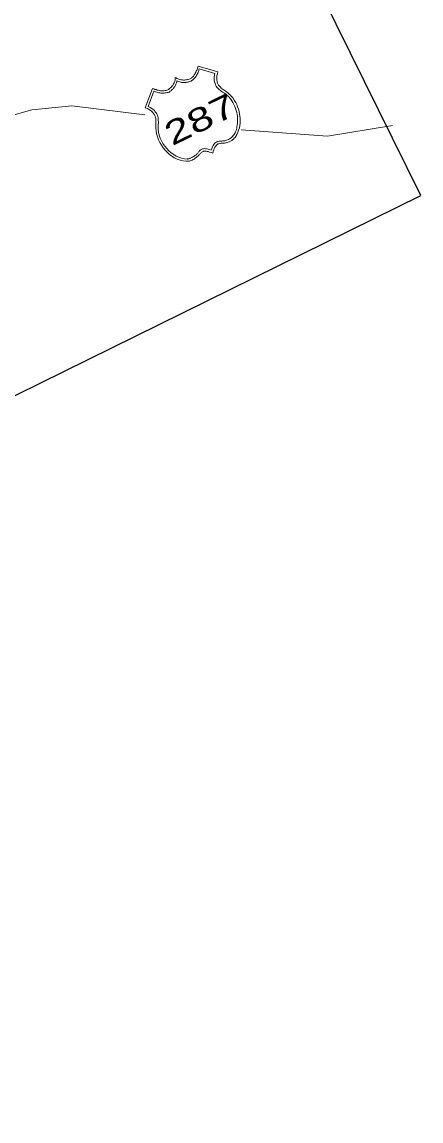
# Model space of a CAD drawing. Extents: x 2356606 to 2371222, y 6973096 to 6982644.
# Drawn here: x 2371136.4 to 2371222.1, y 6980110.7 to 6980347 of the extents above; entities that cross this region are included whole.
import ezdxf

# ---------------------------------------------------------------- set-up
doc = ezdxf.new("R2010")
doc.units = 0
doc.header["$LTSCALE"] = 2
doc.layers.add('62', color=7, linetype='Continuous', lineweight=13)
doc.layers.add('63', color=7, linetype='Continuous', lineweight=13)

msp = doc.modelspace()

# ---------------------------------------------------------------- linework, layer by layer
at = {"layer": '62'}
for p, q in [((2371147.148, 6980328.917), (2371162.799, 6980327.005)), ((2371215.993, 6980324.674), (2371202.01, 6980322.445)), ((2371202.01, 6980322.445), (2371183.47, 6980323.757))]:
    msp.add_line(p, q, dxfattribs=at)
at = {"layer": '62', "lineweight": 25}
msp.add_lwpolyline([(2370613.001, 6980527.892), (2370818.917, 6980110.665), (2371222.081, 6980309.64), (2371016.165, 6980726.869)], dxfattribs=at)
at = {"layer": '62'}
for points in [[(2371147.148, 6980328.917), (2371138.571, 6980328.048), (2371129.118, 6980325.438), (2371112.027, 6980320.969), (2371100.06, 6980322.039), (2371091.911, 6980322.932), (2371081.3, 6980324.295), (2371069.258, 6980328.819), (2371059.239, 6980335.242), (2371048.852, 6980342.862), (2371035.27, 6980351.267), (2371024.817, 6980355.667), (2371015.947, 6980360.773), (2371005.588, 6980367.578), (2370999.855, 6980370.196), (2370987.882, 6980378.49)], [(2371162.878, 6980328.524), (2371164.477, 6980332.651), (2371164.72, 6980332.57), (2371164.969, 6980332.467), (2371165.22, 6980332.415), (2371165.442, 6980332.323), (2371165.696, 6980332.274), (2371165.916, 6980332.23), (2371166.136, 6980332.19), (2371166.377, 6980332.158), (2371166.559, 6980332.146), (2371166.78, 6980332.156), (2371166.982, 6980332.154), (2371167.185, 6980332.204), (2371167.366, 6980332.243), (2371167.524, 6980332.274), (2371167.728, 6980332.372), (2371167.909, 6980332.461), (2371168.011, 6980332.563), (2371168.131, 6980332.673), (2371168.282, 6980332.772), (2371168.414, 6980332.913), (2371168.547, 6980333.054), (2371168.647, 6980333.203), (2371168.781, 6980333.344), (2371168.901, 6980333.503), (2371168.983, 6980333.694), (2371169.085, 6980333.894), (2371169.167, 6980334.085), (2371169.257, 6980334.255), (2371169.288, 6980334.449), (2371169.339, 6980334.648), (2371169.311, 6980334.859), (2371169.341, 6980335.05), (2371169.511, 6980334.96), (2371169.703, 6980334.828), (2371169.903, 6980334.726), (2371170.085, 6980334.664), (2371170.297, 6980334.593), (2371170.516, 6980334.55), (2371170.707, 6980334.521), (2371170.919, 6980334.498), (2371171.127, 6980334.478), (2371171.32, 6980334.448), (2371171.542, 6980334.505), (2371171.725, 6980334.496), (2371171.966, 6980334.564), (2371172.127, 6980334.594), (2371172.348, 6980334.652), (2371172.521, 6980334.713), (2371172.661, 6980334.783), (2371172.832, 6980334.893), (2371172.924, 6980335.012), (2371173.084, 6980335.14), (2371173.216, 6980335.283), (2371173.318, 6980335.434), (2371173.421, 6980335.583), (2371173.552, 6980335.774), (2371173.634, 6980335.965), (2371173.744, 6980336.144), (2371173.816, 6980336.356), (2371173.937, 6980336.567), (2371174.011, 6980336.777), (2371174.09, 6980337.019), (2371174.152, 6980337.251), (2371174.244, 6980337.471), (2371178.496, 6980336.232), (2371178.372, 6980335.818), (2371178.249, 6980335.407), (2371178.235, 6980334.975), (2371178.275, 6980334.542), (2371178.303, 6980334.128), (2371178.389, 6980333.795), (2371178.52, 6980333.534), (2371178.61, 6980333.353), (2371178.732, 6980333.21), (2371178.881, 6980333.061), (2371179.021, 6980332.927), (2371179.201, 6980332.766), (2371179.4, 6980332.614), (2371179.602, 6980332.462), (2371179.834, 6980332.301), (2371180.063, 6980332.139), (2371180.304, 6980331.954), (2371180.535, 6980331.794), (2371180.765, 6980331.58), (2371180.975, 6980331.407), (2371181.165, 6980331.225), (2371181.355, 6980331.044), (2371181.536, 6980330.831), (2371181.684, 6980330.63), (2371181.995, 6980330.155), (2371182.307, 6980329.681), (2371182.534, 6980329.216), (2371182.711, 6980328.703), (2371182.911, 6980328.199), (2371183.05, 6980327.714), (2371183.147, 6980327.21), (2371183.224, 6980326.698), (2371183.293, 6980326.205), (2371183.3, 6980325.68)], [(2371182.569, 6980324.468), (2371182.651, 6980324.758), (2371182.674, 6980325.122), (2371182.695, 6980325.482), (2371182.707, 6980325.865), (2371182.69, 6980326.257), (2371182.662, 6980326.67), (2371182.615, 6980327.073), (2371182.523, 6980327.506), (2371182.427, 6980327.959), (2371182.277, 6980328.363), (2371182.127, 6980328.815), (2371181.921, 6980329.242), (2371181.681, 6980329.673), (2371181.45, 6980330.038), (2371181.232, 6980330.38), (2371180.982, 6980330.633), (2371180.741, 6980330.915), (2371180.48, 6980331.14), (2371180.251, 6980331.352), (2371179.999, 6980331.554), (2371179.739, 6980331.725), (2371179.479, 6980331.899), (2371179.257, 6980332.042), (2371179.047, 6980332.214), (2371178.837, 6980332.386), (2371178.616, 6980332.576), (2371178.457, 6980332.749), (2371178.286, 6980332.942), (2371178.125, 6980333.164), (2371177.966, 6980333.437), (2371177.878, 6980333.77), (2371177.789, 6980334.102), (2371177.721, 6980334.444), (2371177.682, 6980334.825), (2371177.714, 6980335.169), (2371177.787, 6980335.532), (2371177.858, 6980335.893), (2371174.493, 6980336.917), (2371174.423, 6980336.706), (2371174.37, 6980336.503), (2371174.309, 6980336.273), (2371174.228, 6980336.081), (2371174.137, 6980335.863), (2371174.024, 6980335.682), (2371173.914, 6980335.502), (2371173.801, 6980335.32), (2371173.669, 6980335.13), (2371173.557, 6980334.95), (2371173.404, 6980334.798), (2371173.265, 6980334.679), (2371173.132, 6980334.537), (2371173.002, 6980334.449), (2371172.872, 6980334.359), (2371172.739, 6980334.267), (2371172.588, 6980334.22), (2371172.415, 6980334.16), (2371172.236, 6980334.07), (2371172.072, 6980334.041), (2371171.841, 6980334.002), (2371171.68, 6980333.972), (2371171.489, 6980333.953), (2371171.269, 6980333.943), (2371171.086, 6980333.955), (2371170.865, 6980333.947), (2371170.696, 6980333.987), (2371170.494, 6980334.04), (2371170.283, 6980334.061), (2371170.093, 6980334.143), (2371169.902, 6980334.223), (2371169.701, 6980334.326), (2371169.649, 6980334.125), (2371169.608, 6980333.904), (2371169.536, 6980333.743), (2371169.474, 6980333.561), (2371169.374, 6980333.412), (2371169.321, 6980333.261), (2371169.21, 6980333.079), (2371169.13, 6980332.94), (2371169.019, 6980332.808), (2371168.897, 6980332.647), (2371168.795, 6980332.547), (2371168.654, 6980332.43), (2371168.533, 6980332.318), (2371168.421, 6980332.188), (2371168.26, 6980332.109), (2371168.14, 6980331.999), (2371168.007, 6980331.907), (2371167.805, 6980331.81), (2371167.594, 6980331.78), (2371167.381, 6980331.701), (2371167.18, 6980331.702), (2371166.948, 6980331.661), (2371166.709, 6980331.645), (2371166.515, 6980331.675), (2371166.265, 6980331.676), (2371166.024, 6980331.708), (2371165.813, 6980331.73), (2371165.589, 6980331.821), (2371165.351, 6980331.852), (2371165.128, 6980331.943)], [(2371164.768, 6980332.066), (2371163.512, 6980328.812), (2371163.915, 6980328.607), (2371164.275, 6980328.383), (2371164.565, 6980328.152), (2371164.846, 6980327.94), (2371165.055, 6980327.667), (2371165.245, 6980327.435), (2371165.384, 6980327.202), (2371165.506, 6980326.91), (2371165.575, 6980326.616), (2371165.652, 6980326.356), (2371165.692, 6980326.072), (2371165.69, 6980325.77), (2371165.71, 6980325.481), (2371165.707, 6980325.178), (2371165.677, 6980324.886), (2371165.653, 6980324.574), (2371165.65, 6980323.921), (2371165.748, 6980323.265), (2371165.875, 6980322.652), (2371166.112, 6980322.016), (2371166.382, 6980321.421), (2371166.7, 6980320.826), (2371167.099, 6980320.27), (2371167.5, 6980319.765), (2371167.96, 6980319.289), (2371168.481, 6980318.844), (2371169.014, 6980318.478), (2371169.556, 6980318.143), (2371170.126, 6980317.901), (2371170.709, 6980317.687), (2371171.293, 6980317.571), (2371171.855, 6980317.498), (2371171.975, 6980317.508), (2371172.128, 6980317.506), (2371172.278, 6980317.558), (2371172.44, 6980317.637), (2371172.57, 6980317.676), (2371172.734, 6980317.756), (2371172.895, 6980317.835), (2371173.057, 6980317.915), (2371173.228, 6980318.024), (2371173.369, 6980318.096), (2371173.529, 6980318.223), (2371173.682, 6980318.325), (2371173.804, 6980318.434), (2371173.945, 6980318.554), (2371174.057, 6980318.685), (2371174.167, 6980318.765), (2371174.25, 6980318.905), (2371174.358, 6980319.037), (2371174.432, 6980319.145), (2371174.541, 6980319.277), (2371174.664, 6980319.386), (2371174.776, 6980319.466), (2371174.896, 6980319.575), (2371175.037, 6980319.646), (2371175.199, 6980319.676), (2371175.401, 6980319.726), (2371175.581, 6980319.764), (2371175.8, 6980319.722), (2371176.065, 6980319.702), (2371176.365, 6980319.599), (2371176.707, 6980319.517), (2371177.049, 6980319.384), (2371177.181, 6980319.776), (2371177.314, 6980320.117), (2371177.455, 6980320.387), (2371177.609, 6980320.639), (2371177.74, 6980320.83), (2371177.902, 6980320.96), (2371178.043, 6980321.08), (2371178.246, 6980321.18), (2371178.387, 6980321.25), (2371178.547, 6980321.278), (2371178.748, 6980321.327), (2371178.939, 6980321.347), (2371179.123, 6980321.337), (2371179.311, 6980321.357), (2371179.524, 6980321.382), (2371179.747, 6980321.392), (2371179.958, 6980321.421), (2371180.166, 6980321.451), (2371180.36, 6980321.519), (2371180.562, 6980321.62), (2371180.755, 6980321.69), (2371180.946, 6980321.809), (2371181.127, 6980321.899), (2371181.308, 6980322.039), (2371181.491, 6980322.178), (2371181.642, 6980322.328), (2371181.795, 6980322.529), (2371181.936, 6980322.7), (2371182.057, 6980322.91), (2371182.201, 6980323.13), (2371182.282, 6980323.372), (2371182.373, 6980323.644), (2371182.466, 6980323.863), (2371182.517, 6980324.166), (2371182.569, 6980324.468)], [(2371165.128, 6980331.943), (2371164.948, 6980332.003), (2371164.768, 6980332.066)], [(2371163.81, 6980328.105), (2371163.399, 6980328.328), (2371162.878, 6980328.524)], [(2371183.3, 6980325.68), (2371183.266, 6980325.188), (2371183.174, 6980324.716), (2371183.121, 6980324.212), (2371182.935, 6980323.721), (2371182.794, 6980323.247), (2371182.571, 6980322.786), (2371182.438, 6980322.545), (2371182.318, 6980322.337), (2371182.163, 6980322.135), (2371182.002, 6980321.955), (2371181.862, 6980321.783), (2371181.669, 6980321.665), (2371181.467, 6980321.513), (2371181.307, 6980321.386), (2371181.082, 6980321.275), (2371180.88, 6980321.175), (2371180.69, 6980321.107), (2371180.519, 6980321.047), (2371180.288, 6980321.009), (2371180.105, 6980320.968), (2371179.925, 6980320.928), (2371179.722, 6980320.931), (2371179.533, 6980320.912), (2371179.341, 6980320.89), (2371179.19, 6980320.893), (2371178.999, 6980320.873), (2371178.867, 6980320.834), (2371178.686, 6980320.795), (2371178.506, 6980320.756), (2371178.373, 6980320.664), (2371178.232, 6980320.544), (2371178.08, 6980320.395), (2371177.968, 6980320.214), (2371177.837, 6980320.024), (2371177.704, 6980319.783), (2371177.593, 6980319.502), (2371177.49, 6980319.151), (2371177.377, 6980318.769), (2371177.013, 6980318.891), (2371176.715, 6980318.994), (2371176.432, 6980319.106), (2371176.162, 6980319.148), (2371175.961, 6980319.197), (2371175.76, 6980319.198), (2371175.587, 6980319.191), (2371175.428, 6980319.16), (2371175.296, 6980319.122), (2371175.155, 6980319.051), (2371175.034, 6980318.992), (2371174.914, 6980318.883), (2371174.834, 6980318.793), (2371174.7, 6980318.702), (2371174.6, 6980318.552), (2371174.498, 6980318.452), (2371174.408, 6980318.332), (2371174.286, 6980318.221), (2371174.154, 6980318.082), (2371173.992, 6980317.95), (2371173.85, 6980317.831), (2371173.679, 6980317.721), (2371173.518, 6980317.59), (2371173.378, 6980317.472), (2371173.175, 6980317.372), (2371172.992, 6980317.282), (2371172.81, 6980317.191), (2371172.57, 6980317.122), (2371172.366, 6980317.072), (2371172.135, 6980317.034), (2371171.895, 6980317.016), (2371171.642, 6980317.017), (2371171.028, 6980317.09), (2371170.394, 6980317.254), (2371169.772, 6980317.449), (2371169.2, 6980317.745), (2371168.629, 6980318.087), (2371168.108, 6980318.485), (2371167.638, 6980318.93), (2371167.166, 6980319.425), (2371166.736, 6980319.939), (2371166.366, 6980320.485), (2371166.028, 6980321.071), (2371165.737, 6980321.656), (2371165.509, 6980322.273), (2371165.334, 6980322.884), (2371165.216, 6980323.531), (2371165.168, 6980324.134), (2371165.148, 6980324.376), (2371165.14, 6980324.647), (2371165.162, 6980324.909), (2371165.163, 6980325.209), (2371165.168, 6980325.512), (2371165.167, 6980325.813), (2371165.148, 6980326.107), (2371165.079, 6980326.397), (2371165, 6980326.71), (2371164.852, 6980327.015), (2371164.682, 6980327.305), (2371164.451, 6980327.57), (2371164.162, 6980327.853), (2371163.81, 6980328.105)]]:
    msp.add_lwpolyline(points, dxfattribs=at)
at = {"layer": '63'}
for p, q in [((2371147.148, 6980328.917), (2371162.799, 6980327.005)), ((2371215.993, 6980324.674), (2371202.01, 6980322.445)), ((2371202.01, 6980322.445), (2371183.47, 6980323.757))]:
    msp.add_line(p, q, dxfattribs=at)
at = {"layer": '63', "lineweight": 25}
msp.add_lwpolyline([(2370613.001, 6980527.892), (2370818.917, 6980110.665), (2371222.081, 6980309.64), (2371016.165, 6980726.869)], dxfattribs=at)
at = {"layer": '63'}
for points in [[(2371147.148, 6980328.917), (2371138.571, 6980328.048), (2371129.118, 6980325.438), (2371112.027, 6980320.969), (2371100.06, 6980322.039), (2371091.911, 6980322.932), (2371081.3, 6980324.295), (2371069.258, 6980328.819), (2371059.239, 6980335.242), (2371048.852, 6980342.862), (2371035.27, 6980351.267), (2371024.817, 6980355.667), (2371015.947, 6980360.773), (2371005.588, 6980367.578), (2370999.855, 6980370.196), (2370987.882, 6980378.49)], [(2371162.878, 6980328.524), (2371164.477, 6980332.651), (2371164.72, 6980332.57), (2371164.969, 6980332.467), (2371165.22, 6980332.415), (2371165.442, 6980332.323), (2371165.696, 6980332.274), (2371165.916, 6980332.23), (2371166.136, 6980332.19), (2371166.377, 6980332.158), (2371166.559, 6980332.146), (2371166.78, 6980332.156), (2371166.982, 6980332.154), (2371167.185, 6980332.204), (2371167.366, 6980332.243), (2371167.524, 6980332.274), (2371167.728, 6980332.372), (2371167.909, 6980332.461), (2371168.011, 6980332.563), (2371168.131, 6980332.673), (2371168.282, 6980332.772), (2371168.414, 6980332.913), (2371168.547, 6980333.054), (2371168.647, 6980333.203), (2371168.781, 6980333.344), (2371168.901, 6980333.503), (2371168.983, 6980333.694), (2371169.085, 6980333.894), (2371169.167, 6980334.085), (2371169.257, 6980334.255), (2371169.288, 6980334.449), (2371169.339, 6980334.648), (2371169.311, 6980334.859), (2371169.341, 6980335.05), (2371169.511, 6980334.96), (2371169.703, 6980334.828), (2371169.903, 6980334.726), (2371170.085, 6980334.664), (2371170.297, 6980334.593), (2371170.516, 6980334.55), (2371170.707, 6980334.521), (2371170.919, 6980334.498), (2371171.127, 6980334.478), (2371171.32, 6980334.448), (2371171.542, 6980334.505), (2371171.725, 6980334.496), (2371171.966, 6980334.564), (2371172.127, 6980334.594), (2371172.348, 6980334.652), (2371172.521, 6980334.713), (2371172.661, 6980334.783), (2371172.832, 6980334.893), (2371172.924, 6980335.012), (2371173.084, 6980335.14), (2371173.216, 6980335.283), (2371173.318, 6980335.434), (2371173.421, 6980335.583), (2371173.552, 6980335.774), (2371173.634, 6980335.965), (2371173.744, 6980336.144), (2371173.816, 6980336.356), (2371173.937, 6980336.567), (2371174.011, 6980336.777), (2371174.09, 6980337.019), (2371174.152, 6980337.251), (2371174.244, 6980337.471), (2371178.496, 6980336.232), (2371178.372, 6980335.818), (2371178.249, 6980335.407), (2371178.235, 6980334.975), (2371178.275, 6980334.542), (2371178.303, 6980334.128), (2371178.389, 6980333.795), (2371178.52, 6980333.534), (2371178.61, 6980333.353), (2371178.732, 6980333.21), (2371178.881, 6980333.061), (2371179.021, 6980332.927), (2371179.201, 6980332.766), (2371179.4, 6980332.614), (2371179.602, 6980332.462), (2371179.834, 6980332.301), (2371180.063, 6980332.139), (2371180.304, 6980331.954), (2371180.535, 6980331.794), (2371180.765, 6980331.58), (2371180.975, 6980331.407), (2371181.165, 6980331.225), (2371181.355, 6980331.044), (2371181.536, 6980330.831), (2371181.684, 6980330.63), (2371181.995, 6980330.155), (2371182.307, 6980329.681), (2371182.534, 6980329.216), (2371182.711, 6980328.703), (2371182.911, 6980328.199), (2371183.05, 6980327.714), (2371183.147, 6980327.21), (2371183.224, 6980326.698), (2371183.293, 6980326.205), (2371183.3, 6980325.68)], [(2371182.569, 6980324.468), (2371182.651, 6980324.758), (2371182.674, 6980325.122), (2371182.695, 6980325.482), (2371182.707, 6980325.865), (2371182.69, 6980326.257), (2371182.662, 6980326.67), (2371182.615, 6980327.073), (2371182.523, 6980327.506), (2371182.427, 6980327.959), (2371182.277, 6980328.363), (2371182.127, 6980328.815), (2371181.921, 6980329.242), (2371181.681, 6980329.673), (2371181.45, 6980330.038), (2371181.232, 6980330.38), (2371180.982, 6980330.633), (2371180.741, 6980330.915), (2371180.48, 6980331.14), (2371180.251, 6980331.352), (2371179.999, 6980331.554), (2371179.739, 6980331.725), (2371179.479, 6980331.899), (2371179.257, 6980332.042), (2371179.047, 6980332.214), (2371178.837, 6980332.386), (2371178.616, 6980332.576), (2371178.457, 6980332.749), (2371178.286, 6980332.942), (2371178.125, 6980333.164), (2371177.966, 6980333.437), (2371177.878, 6980333.77), (2371177.789, 6980334.102), (2371177.721, 6980334.444), (2371177.682, 6980334.825), (2371177.714, 6980335.169), (2371177.787, 6980335.532), (2371177.858, 6980335.893), (2371174.493, 6980336.917), (2371174.423, 6980336.706), (2371174.37, 6980336.503), (2371174.309, 6980336.273), (2371174.228, 6980336.081), (2371174.137, 6980335.863), (2371174.024, 6980335.682), (2371173.914, 6980335.502), (2371173.801, 6980335.32), (2371173.669, 6980335.13), (2371173.557, 6980334.95), (2371173.404, 6980334.798), (2371173.265, 6980334.679), (2371173.132, 6980334.537), (2371173.002, 6980334.449), (2371172.872, 6980334.359), (2371172.739, 6980334.267), (2371172.588, 6980334.22), (2371172.415, 6980334.16), (2371172.236, 6980334.07), (2371172.072, 6980334.041), (2371171.841, 6980334.002), (2371171.68, 6980333.972), (2371171.489, 6980333.953), (2371171.269, 6980333.943), (2371171.086, 6980333.955), (2371170.865, 6980333.947), (2371170.696, 6980333.987), (2371170.494, 6980334.04), (2371170.283, 6980334.061), (2371170.093, 6980334.143), (2371169.902, 6980334.223), (2371169.701, 6980334.326), (2371169.649, 6980334.125), (2371169.608, 6980333.904), (2371169.536, 6980333.743), (2371169.474, 6980333.561), (2371169.374, 6980333.412), (2371169.321, 6980333.261), (2371169.21, 6980333.079), (2371169.13, 6980332.94), (2371169.019, 6980332.808), (2371168.897, 6980332.647), (2371168.795, 6980332.547), (2371168.654, 6980332.43), (2371168.533, 6980332.318), (2371168.421, 6980332.188), (2371168.26, 6980332.109), (2371168.14, 6980331.999), (2371168.007, 6980331.907), (2371167.805, 6980331.81), (2371167.594, 6980331.78), (2371167.381, 6980331.701), (2371167.18, 6980331.702), (2371166.948, 6980331.661), (2371166.709, 6980331.645), (2371166.515, 6980331.675), (2371166.265, 6980331.676), (2371166.024, 6980331.708), (2371165.813, 6980331.73), (2371165.589, 6980331.821), (2371165.351, 6980331.852), (2371165.128, 6980331.943)], [(2371164.768, 6980332.066), (2371163.512, 6980328.812), (2371163.915, 6980328.607), (2371164.275, 6980328.383), (2371164.565, 6980328.152), (2371164.846, 6980327.94), (2371165.055, 6980327.667), (2371165.245, 6980327.435), (2371165.384, 6980327.202), (2371165.506, 6980326.91), (2371165.575, 6980326.616), (2371165.652, 6980326.356), (2371165.692, 6980326.072), (2371165.69, 6980325.77), (2371165.71, 6980325.481), (2371165.707, 6980325.178), (2371165.677, 6980324.886), (2371165.653, 6980324.574), (2371165.65, 6980323.921), (2371165.748, 6980323.265), (2371165.875, 6980322.652), (2371166.112, 6980322.016), (2371166.382, 6980321.421), (2371166.7, 6980320.826), (2371167.099, 6980320.27), (2371167.5, 6980319.765), (2371167.96, 6980319.289), (2371168.481, 6980318.844), (2371169.014, 6980318.478), (2371169.556, 6980318.143), (2371170.126, 6980317.901), (2371170.709, 6980317.687), (2371171.293, 6980317.571), (2371171.855, 6980317.498), (2371171.975, 6980317.508), (2371172.128, 6980317.506), (2371172.278, 6980317.558), (2371172.44, 6980317.637), (2371172.57, 6980317.676), (2371172.734, 6980317.756), (2371172.895, 6980317.835), (2371173.057, 6980317.915), (2371173.228, 6980318.024), (2371173.369, 6980318.096), (2371173.529, 6980318.223), (2371173.682, 6980318.325), (2371173.804, 6980318.434), (2371173.945, 6980318.554), (2371174.057, 6980318.685), (2371174.167, 6980318.765), (2371174.25, 6980318.905), (2371174.358, 6980319.037), (2371174.432, 6980319.145), (2371174.541, 6980319.277), (2371174.664, 6980319.386), (2371174.776, 6980319.466), (2371174.896, 6980319.575), (2371175.037, 6980319.646), (2371175.199, 6980319.676), (2371175.401, 6980319.726), (2371175.581, 6980319.764), (2371175.8, 6980319.722), (2371176.065, 6980319.702), (2371176.365, 6980319.599), (2371176.707, 6980319.517), (2371177.049, 6980319.384), (2371177.181, 6980319.776), (2371177.314, 6980320.117), (2371177.455, 6980320.387), (2371177.609, 6980320.639), (2371177.74, 6980320.83), (2371177.902, 6980320.96), (2371178.043, 6980321.08), (2371178.246, 6980321.18), (2371178.387, 6980321.25), (2371178.547, 6980321.278), (2371178.748, 6980321.327), (2371178.939, 6980321.347), (2371179.123, 6980321.337), (2371179.311, 6980321.357), (2371179.524, 6980321.382), (2371179.747, 6980321.392), (2371179.958, 6980321.421), (2371180.166, 6980321.451), (2371180.36, 6980321.519), (2371180.562, 6980321.62), (2371180.755, 6980321.69), (2371180.946, 6980321.809), (2371181.127, 6980321.899), (2371181.308, 6980322.039), (2371181.491, 6980322.178), (2371181.642, 6980322.328), (2371181.795, 6980322.529), (2371181.936, 6980322.7), (2371182.057, 6980322.91), (2371182.201, 6980323.13), (2371182.282, 6980323.372), (2371182.373, 6980323.644), (2371182.466, 6980323.863), (2371182.517, 6980324.166), (2371182.569, 6980324.468)], [(2371165.128, 6980331.943), (2371164.948, 6980332.003), (2371164.768, 6980332.066)], [(2371163.81, 6980328.105), (2371163.399, 6980328.328), (2371162.878, 6980328.524)], [(2371183.3, 6980325.68), (2371183.266, 6980325.188), (2371183.174, 6980324.716), (2371183.121, 6980324.212), (2371182.935, 6980323.721), (2371182.794, 6980323.247), (2371182.571, 6980322.786), (2371182.438, 6980322.545), (2371182.318, 6980322.337), (2371182.163, 6980322.135), (2371182.002, 6980321.955), (2371181.862, 6980321.783), (2371181.669, 6980321.665), (2371181.467, 6980321.513), (2371181.307, 6980321.386), (2371181.082, 6980321.275), (2371180.88, 6980321.175), (2371180.69, 6980321.107), (2371180.519, 6980321.047), (2371180.288, 6980321.009), (2371180.105, 6980320.968), (2371179.925, 6980320.928), (2371179.722, 6980320.931), (2371179.533, 6980320.912), (2371179.341, 6980320.89), (2371179.19, 6980320.893), (2371178.999, 6980320.873), (2371178.867, 6980320.834), (2371178.686, 6980320.795), (2371178.506, 6980320.756), (2371178.373, 6980320.664), (2371178.232, 6980320.544), (2371178.08, 6980320.395), (2371177.968, 6980320.214), (2371177.837, 6980320.024), (2371177.704, 6980319.783), (2371177.593, 6980319.502), (2371177.49, 6980319.151), (2371177.377, 6980318.769), (2371177.013, 6980318.891), (2371176.715, 6980318.994), (2371176.432, 6980319.106), (2371176.162, 6980319.148), (2371175.961, 6980319.197), (2371175.76, 6980319.198), (2371175.587, 6980319.191), (2371175.428, 6980319.16), (2371175.296, 6980319.122), (2371175.155, 6980319.051), (2371175.034, 6980318.992), (2371174.914, 6980318.883), (2371174.834, 6980318.793), (2371174.7, 6980318.702), (2371174.6, 6980318.552), (2371174.498, 6980318.452), (2371174.408, 6980318.332), (2371174.286, 6980318.221), (2371174.154, 6980318.082), (2371173.992, 6980317.95), (2371173.85, 6980317.831), (2371173.679, 6980317.721), (2371173.518, 6980317.59), (2371173.378, 6980317.472), (2371173.175, 6980317.372), (2371172.992, 6980317.282), (2371172.81, 6980317.191), (2371172.57, 6980317.122), (2371172.366, 6980317.072), (2371172.135, 6980317.034), (2371171.895, 6980317.016), (2371171.642, 6980317.017), (2371171.028, 6980317.09), (2371170.394, 6980317.254), (2371169.772, 6980317.449), (2371169.2, 6980317.745), (2371168.629, 6980318.087), (2371168.108, 6980318.485), (2371167.638, 6980318.93), (2371167.166, 6980319.425), (2371166.736, 6980319.939), (2371166.366, 6980320.485), (2371166.028, 6980321.071), (2371165.737, 6980321.656), (2371165.509, 6980322.273), (2371165.334, 6980322.884), (2371165.216, 6980323.531), (2371165.168, 6980324.134), (2371165.148, 6980324.376), (2371165.14, 6980324.647), (2371165.162, 6980324.909), (2371165.163, 6980325.209), (2371165.168, 6980325.512), (2371165.167, 6980325.813), (2371165.148, 6980326.107), (2371165.079, 6980326.397), (2371165, 6980326.71), (2371164.852, 6980327.015), (2371164.682, 6980327.305), (2371164.451, 6980327.57), (2371164.162, 6980327.853), (2371163.81, 6980328.105)]]:
    msp.add_lwpolyline(points, dxfattribs=at)

# ---------------------------------------------------------------- texts
at = {"layer": '62', "width": 1.4}
msp.add_text('287', height=5.099, rotation=26.268, dxfattribs=at).set_placement((2371168.65, 6980320.233))
at = {"layer": '63', "width": 1.4}
msp.add_text('287', height=5.099, rotation=26.268, dxfattribs=at).set_placement((2371168.65, 6980320.233))

doc.saveas('drawing.dxf')
